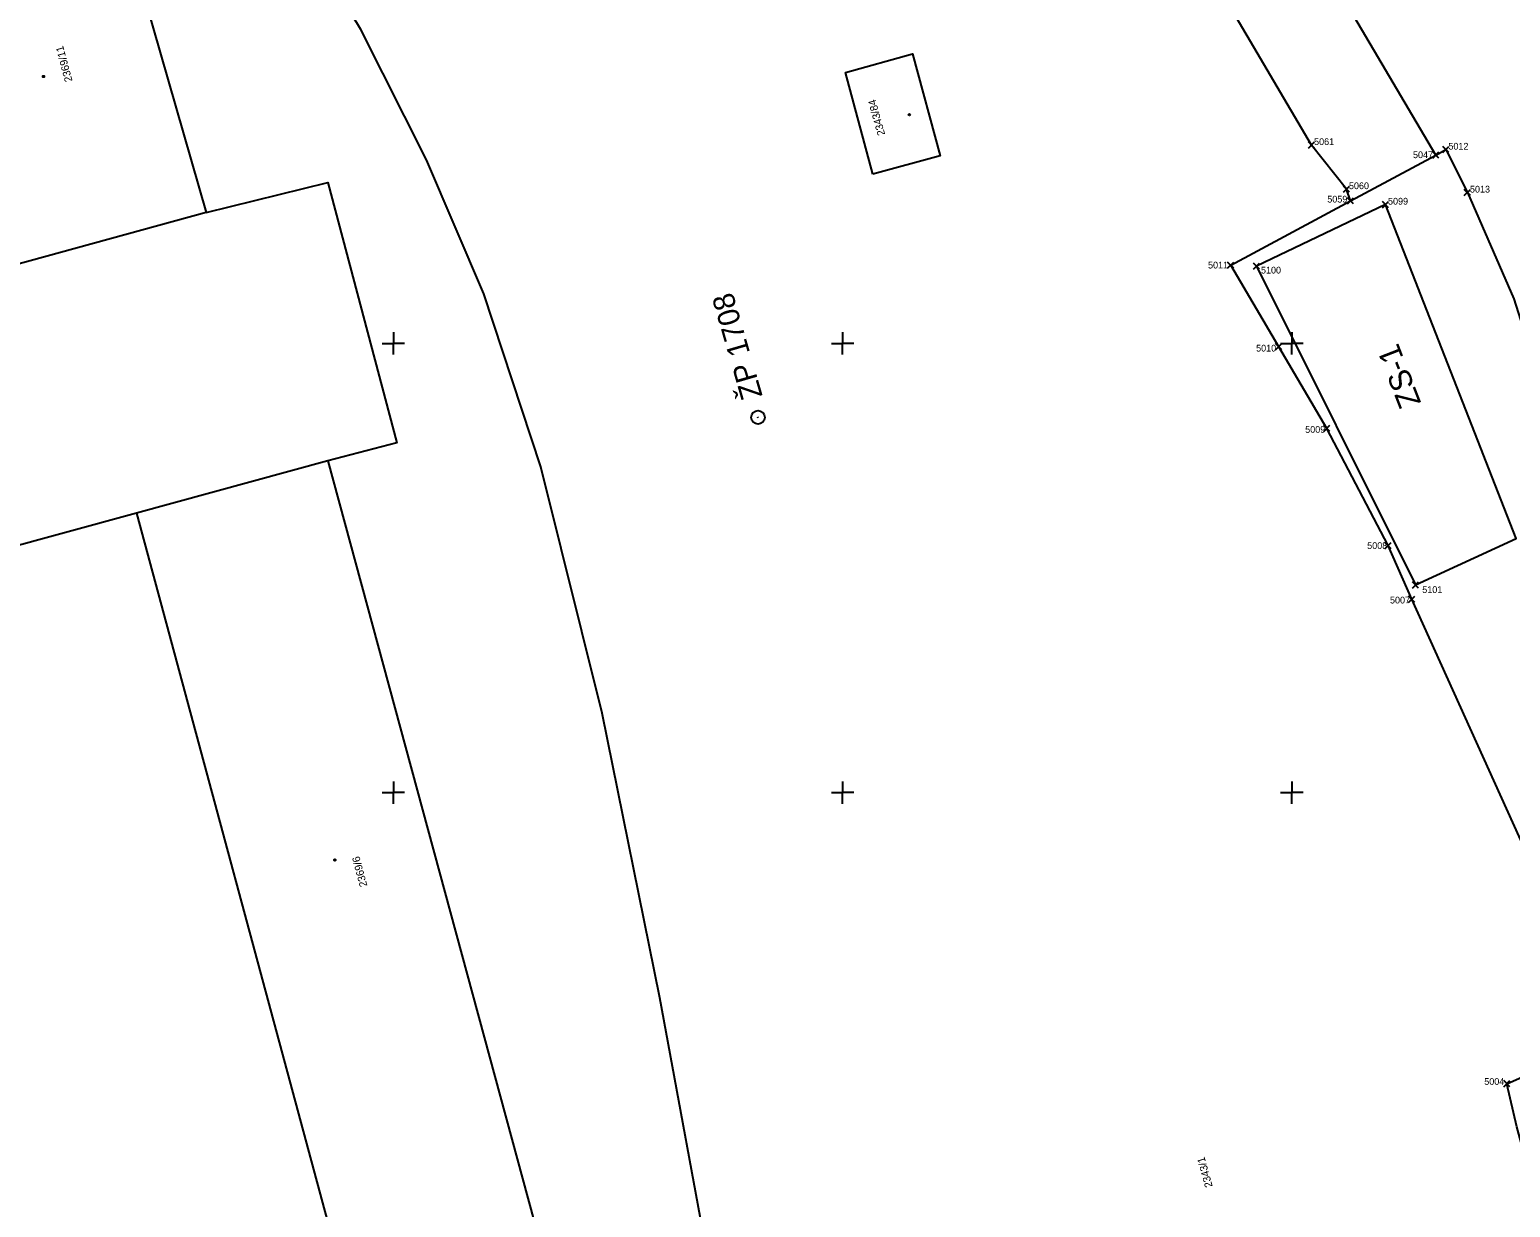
# Model space of a CAD drawing. Extents: x -821172 to -820632, y -1070921 to -1069931.
# Drawn here: x -820990.5 to -820825.7, y -1070396.2 to -1070265.1 of the extents above; entities that cross this region are included whole.
import ezdxf

# ---------------------------------------------------------------- set-up
doc = ezdxf.new("R2010")
doc.units = 0
for name, color, linetype in [('Sit', 7, 'Continuous'), ('VB_bod_DZ', 7, 'Continuous'), ('Vrstva 52', 7, 'Continuous'), ('Vrstva 53', 7, 'Continuous'), ('Vrstva 55', 7, 'Continuous'), ('Vrstva 57', 7, 'Continuous'), ('Vrstva 59', 7, 'Continuous'), ('ZBP', 7, 'Continuous')]:
    doc.layers.add(name, color=color, linetype=linetype)

msp = doc.modelspace()

# ---------------------------------------------------------------- linework, layer by layer
at = {"layer": 'Sit'}
for p, q in [((-820950, -1070298.75), (-820950, -1070300)), ((-820900, -1070298.75), (-820900, -1070300)), ((-820850, -1070298.75), (-820850, -1070300)), ((-820951.25, -1070300), (-820950, -1070300)), ((-820948.75, -1070300), (-820950, -1070300)), ((-820950, -1070301.25), (-820950, -1070300)), ((-820901.25, -1070300), (-820900, -1070300)), ((-820898.75, -1070300), (-820900, -1070300)), ((-820900, -1070301.25), (-820900, -1070300)), ((-820851.25, -1070300), (-820850, -1070300)), ((-820848.75, -1070300), (-820850, -1070300)), ((-820850, -1070301.25), (-820850, -1070300)), ((-820950, -1070348.75), (-820950, -1070350)), ((-820900, -1070348.75), (-820900, -1070350)), ((-820850, -1070348.75), (-820850, -1070350)), ((-820951.25, -1070350), (-820950, -1070350)), ((-820948.75, -1070350), (-820950, -1070350)), ((-820950, -1070351.25), (-820950, -1070350)), ((-820901.25, -1070350), (-820900, -1070350)), ((-820898.75, -1070350), (-820900, -1070350)), ((-820900, -1070351.25), (-820900, -1070350)), ((-820851.25, -1070350), (-820850, -1070350)), ((-820848.75, -1070350), (-820850, -1070350)), ((-820850, -1070351.25), (-820850, -1070350))]:
    msp.add_line(p, q, dxfattribs=at)
at = {"layer": 'VB_bod_DZ'}
for p, q in [((-820848.15, -1070278.27), (-820847.47, -1070277.58)), ((-820847.47, -1070278.27), (-820848.15, -1070277.58)), ((-820834.33, -1070279.38), (-820833.64, -1070278.7)), ((-820833.64, -1070279.38), (-820834.33, -1070278.7)), ((-820833.2, -1070278.78), (-820832.52, -1070278.09)), ((-820832.52, -1070278.78), (-820833.2, -1070278.09)), ((-820844.27, -1070283.18), (-820843.59, -1070282.5)), ((-820843.59, -1070283.18), (-820844.27, -1070282.5)), ((-820830.81, -1070283.56), (-820830.12, -1070282.87)), ((-820830.12, -1070283.56), (-820830.81, -1070282.87)), ((-820843.82, -1070284.48), (-820843.13, -1070283.79)), ((-820843.13, -1070284.48), (-820843.82, -1070283.79)), ((-820839.92, -1070284.91), (-820839.23, -1070284.22)), ((-820839.23, -1070284.91), (-820839.92, -1070284.22)), ((-820857.16, -1070291.63), (-820856.47, -1070290.95)), ((-820856.47, -1070291.63), (-820857.16, -1070290.95)), ((-820854.29, -1070291.76), (-820853.6, -1070291.08)), ((-820853.6, -1070291.76), (-820854.29, -1070291.08)), ((-820851.81, -1070300.72), (-820851.12, -1070300.03)), ((-820851.12, -1070300.72), (-820851.81, -1070300.03)), ((-820846.46, -1070309.8), (-820845.77, -1070309.12)), ((-820845.77, -1070309.8), (-820846.46, -1070309.12)), ((-820839.64, -1070322.85), (-820838.95, -1070322.16)), ((-820838.95, -1070322.85), (-820839.64, -1070322.16)), ((-820836.59, -1070327.24), (-820835.9, -1070326.55)), ((-820835.9, -1070327.24), (-820836.59, -1070326.55)), ((-820837.01, -1070328.83), (-820836.32, -1070328.14)), ((-820836.32, -1070328.83), (-820837.01, -1070328.14)), ((-820826.42, -1070382.74), (-820825.73, -1070382.05)), ((-820825.73, -1070382.74), (-820826.42, -1070382.05))]:
    msp.add_line(p, q, dxfattribs=at)
at = {"layer": 'Vrstva 52'}
for points in [[(-820843.48, -1070284.13), (-820843.93, -1070282.84), (-820847.81, -1070277.93), (-820871.73, -1070237.25), (-820885.29, -1070218.2), (-820887.54, -1070214.67), (-820897.96, -1070197.77), (-820903.32, -1070188.38), (-820912.12, -1070190.61), (-820919.97, -1070176.29), (-820926.49, -1070162.4), (-820934.28, -1070147.4), (-820935.96, -1070145.11), (-820960.28, -1070123.34), (-820989.85, -1070096.95), (-820989.01, -1070086.94)], [(-820833.99, -1070279.04), (-820843.49, -1070262.96), (-820852.87, -1070246.42), (-820862.31, -1070231.6), (-820865.19, -1070221.48), (-820871.51, -1070211.52), (-820874.37, -1070206.78), (-820882.74, -1070199.34)], [(-820782.06, -1070569.19), (-820823.93, -1070391.03), (-820824.95, -1070387.21), (-820826.08, -1070382.39), (-820815.22, -1070377.53), (-820822.07, -1070360.7), (-820836.66, -1070328.48), (-820839.3, -1070322.5), (-820846.11, -1070309.46), (-820851.46, -1070300.37), (-820856.81, -1070291.29), (-820843.48, -1070284.13), (-820833.99, -1070279.04), (-820832.86, -1070278.44), (-820830.46, -1070283.22), (-820825.29, -1070295.05), (-820815.49, -1070325.84), (-820807.6, -1070359.39), (-820795.41, -1070386.91), (-820791.18, -1070389.77), (-820780.82, -1070405.78)]]:
    msp.add_lwpolyline(points, dxfattribs=at)
msp.add_lwpolyline([(-820839.58, -1070284.56), (-820853.94, -1070291.42), (-820836.24, -1070326.89), (-820825.03, -1070321.71)], close=True, dxfattribs=at)
at = {"layer": 'Vrstva 53'}
msp.add_lwpolyline([(-820793.34, -1070807.43), (-820797.89, -1070798.01), (-820802.49, -1070786.9), (-820807.86, -1070771.6), (-820839.34, -1070671.73), (-820847.49, -1070649.05), (-820862.12, -1070611.55), (-820870.18, -1070588.9), (-820893.88, -1070513.71), (-820901.78, -1070488.65), (-820908.48, -1070465.88), (-820912.77, -1070441.75), (-820907.91, -1070440.8), (-820914.43, -1070404.83), (-820920.34, -1070372.85), (-820926.76, -1070341.17), (-820933.59, -1070313.73), (-820939.94, -1070294.5), (-820946.33, -1070279.59), (-820953.63, -1070265.09), (-820959.73, -1070254.91)], dxfattribs=at)
at = {"layer": 'Vrstva 55'}
for p, q in [((-820970.82, -1070285.44), (-820998.99, -1070293.15)), ((-820957.29, -1070313.09), (-820978.59, -1070318.91)), ((-820957.29, -1070313.09), (-820933.62, -1070400.37)), ((-820978.59, -1070318.91), (-821050.57, -1070338.41)), ((-820978.59, -1070318.91), (-820955.07, -1070406.16))]:
    msp.add_line(p, q, dxfattribs=at)
for points in [[(-820793.34, -1070807.43), (-820797.89, -1070798.01), (-820802.49, -1070786.9), (-820807.86, -1070771.6), (-820839.34, -1070671.73), (-820847.49, -1070649.05), (-820862.12, -1070611.55), (-820870.18, -1070588.9), (-820893.88, -1070513.71), (-820901.78, -1070488.65), (-820908.48, -1070465.88), (-820912.77, -1070441.75), (-820907.91, -1070440.8), (-820914.43, -1070404.83), (-820920.34, -1070372.85), (-820926.76, -1070341.17), (-820933.59, -1070313.73), (-820939.94, -1070294.5), (-820946.33, -1070279.59), (-820953.63, -1070265.09), (-820959.73, -1070254.91)], [(-820983.06, -1070258.22), (-820977.6, -1070261.97), (-820970.82, -1070285.44)], [(-820896.64, -1070281.17), (-820899.7, -1070269.85), (-820892.24, -1070267.79), (-820889.16, -1070279.12), (-820896.64, -1070281.17)], [(-820970.82, -1070285.44), (-820957.3, -1070282.09), (-820949.63, -1070311.06), (-820957.29, -1070313.09)]]:
    msp.add_lwpolyline(points, dxfattribs=at)
at = {"layer": 'Vrstva 59'}
for centre in [(-820988.94, -1070270.3), (-820892.57, -1070274.54), (-820956.52, -1070357.49)]:
    msp.add_circle(centre, 0.0875, dxfattribs=at)
at = {"layer": 'ZBP'}
msp.add_line((-820909.41, -1070308.28), (-820909.43, -1070308.19), dxfattribs=at)
msp.add_circle((-820909.42, -1070308.24), 0.756, dxfattribs=at)

# ---------------------------------------------------------------- texts
at = {"layer": 'VB_bod_DZ'}
for s, p in [(' 5061', (-820847.81, -1070277.93)), (' 5012', (-820832.86, -1070278.44)), (' 5047', (-820836.8, -1070279.39)), (' 5060', (-820843.93, -1070282.84)), (' 5013', (-820830.46, -1070283.22)), (' 5059', (-820846.34, -1070284.33)), (' 5099', (-820839.58, -1070284.56)), (' 5011', (-820859.61, -1070291.67)), (' 5100', (-820853.72, -1070292.23)), (' 5010', (-820854.26, -1070300.91)), (' 5009', (-820848.8, -1070309.96)), (' 5008', (-820841.9, -1070322.88)), (' 5101', (-820835.77, -1070327.78)), (' 5007', (-820839.36, -1070328.95)), (' 5004', (-820828.87, -1070382.52))]:
    msp.add_text(s, height=0.75, dxfattribs=at).set_placement(p)
at = {"layer": 'Vrstva 52'}
msp.add_text('ZS-1', height=2.5, rotation=111.2148, dxfattribs=at).set_placement((-820835.59, -1070306.62))
at = {"layer": 'Vrstva 57'}
for s, rotation, p in [('2369/11', 105, (-820985.71, -1070270.79)), ('2343/84', 105.5289, (-820895.26, -1070276.75)), ('2369/6', 105, (-820952.89, -1070360.37)), ('2343/1', 105.5289, (-820858.81, -1070393.82))]:
    msp.add_text(s, height=0.85, rotation=rotation, dxfattribs=at).set_placement(p)
at = {"layer": 'ZBP'}
msp.add_text('ŽP 1708', height=2.4, rotation=106.1993, dxfattribs=at).set_placement((-820908.89, -1070305.85))

doc.saveas('drawing.dxf')
